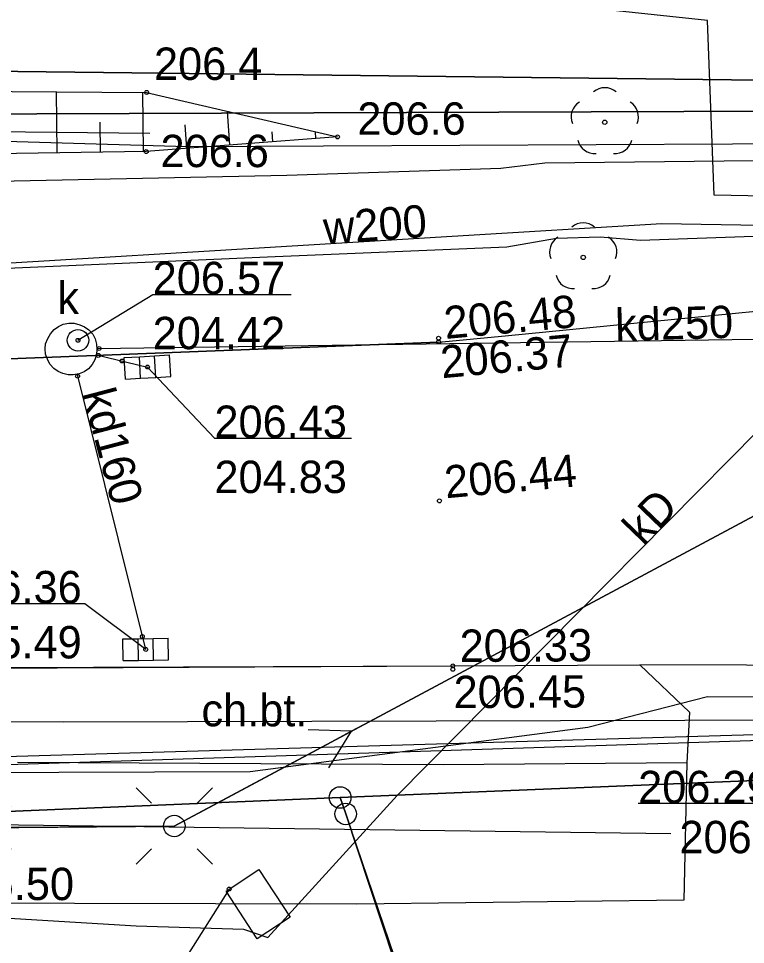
# Model space of a CAD drawing. Extents: x 6512400 to 6513200, y 6022500 to 6022750.
# Drawn here: x 6512747.42 to 6512764.26, y 6022670.32 to 6022691.76 of the extents above; entities that cross this region are included whole.
import ezdxf

# ---------------------------------------------------------------- set-up
doc = ezdxf.new("R2010")
doc.units = 0
for name, color, linetype in [('202-punkt graniczny', 7, 'Continuous'), ('216-obręb ewidencyjny', 7, 'Continuous'), ('218-kontur użytku gruntowego', 7, 'Continuous'), ('219-działka ewidencyjna', 7, 'Continuous'), ('820-Skarpa nieumocniona', 7, 'Continuous'), ('823-Szczyt skarpy nieumocninej', 7, 'Continuous'), ('824-Podnóże skarpy nieumocninej', 7, 'Continuous'), ('903-Żywopłot', 7, 'Continuous'), ('chodnik', 7, 'Continuous'), ('chodnik (powierzchnia)', 7, 'Continuous'), ('chodnik (powierzchnia)-Atr17', 7, 'Continuous'), ('drzewo liściaste (punkt)', 7, 'Continuous'), ('inny obiekt zagospodarowania terenu', 7, 'Continuous'), ('jezdnia (powierzchnia)', 7, 'Continuous'), ('komora podziemna - przewód kanalizacyjny (powierzchnia)', 7, 'Continuous'), ('kratka ściekowa (punkt)', 7, 'Continuous'), ('krawężnik (linia)', 7, 'Continuous'), ('latarnia na słupie lub maszcie (punkt)', 7, 'Continuous'), ('pikieta sztuczna-Atr2', 7, 'Continuous'), ('przewód elektroenergetyczny (linia)', 7, 'Continuous'), ('przewód elektroenergetyczny niskiego napięcia (linia)', 7, 'Continuous'), ('przewód elektroenergetyczny niskiego napięcia (linia) - symbol', 7, 'Continuous'), ('przewód gazowy (linia)', 7, 'Continuous'), ('przewód kanalizacyjny (linia)', 7, 'Continuous'), ('przewód kanalizacyjny (linia)-Atr1', 7, 'Continuous'), ('przewód telekomunikacyjny (linia)', 7, 'Continuous'), ('przewód wodociągowy (linia)', 7, 'Continuous'), ('przewód wodociągowy (linia)-Atr1', 7, 'Continuous'), ('punkt o określonej wysokości (sieć kanalizacyjna)', 7, 'Continuous'), ('punkt o określonej wysokości (sieć kanalizacyjna)-Atr2', 7, 'Continuous'), ('punkt o określonej wysokości (sieć kanalizacyjna)-Atr3', 7, 'Continuous'), ('punkt o określonej wysokości (sieć wodociągowa)-Atr2', 7, 'Continuous'), ('punkt wysokościowy naturalny', 7, 'Continuous'), ('punkt wysokościowy naturalny-Atr2', 7, 'Continuous'), ('punkt wysokościowy sztuczny', 7, 'Continuous'), ('punkt wysokościowy sztuczny-Atr2', 7, 'Continuous'), ('słup (punkt)', 7, 'Continuous'), ('właz okrągły - siec kanalizacyjna (punkt)', 7, 'Continuous'), ('właz okrągły - siec kanalizacyjna (punkt)-Atr17', 7, 'Continuous')]:
    doc.layers.add(name, color=color, linetype=linetype)

# ---------------------------------------------------------------- blocks, each defined once
blk = doc.blocks.new('202')
blk.add_circle((0, 0), 0.25)
blk = doc.blocks.new('PW01')
blk.add_circle((0, 0), 0.045)
blk = doc.blocks.new('OP021')
blk.add_circle((0, 0), 0.05)
for centre, start, end in [((0, 0.4), 49.272, 130.728), ((-0.38, 0.124), 121.308, 202.548), ((0.38, 0.124), 337.452, 58.692), ((-0.235, -0.324), 193.221, 274.871), ((0.235, -0.324), 265.129, 346.779)]:
    blk.add_arc(centre, 0.4, start, end)
blk = doc.blocks.new('US22')
blk.add_circle((0, 0), 0.25)
blk = doc.blocks.new('US05')
for p, q in [((-0.525, -0.25), (-0.525, 0.25)), ((-0.525, 0.25), (-0.175, 0.25)), ((-0.175, -0.25), (-0.175, 0.25)), ((-0.175, 0.25), (0.175, 0.25)), ((0.175, -0.25), (0.175, 0.25)), ((0.175, 0.25), (0.525, 0.25)), ((0.525, -0.25), (0.525, 0.25)), ((-0.525, -0.25), (-0.175, -0.25)), ((-0.175, -0.25), (0.175, -0.25)), ((0.175, -0.25), (0.525, -0.25))]:
    blk.add_line(p, q)
blk = doc.blocks.new('PW02')
blk.add_circle((0, 0), 0.045)
blk = doc.blocks.new('PE04')
for p, q in [((4.65, 0), (3.784, 0.5)), ((0.65, 0), (0, 0)), ((0.65, 0), (1.65, 0)), ((1.65, 0), (2.65, 0)), ((2.65, 0), (3.65, 0)), ((3.65, 0), (4.65, 0)), ((4.65, 0), (3.784, -0.5)), ((4.65, 0), (5, 0))]:
    blk.add_line(p, q)
blk = doc.blocks.new('SM011')
for p, q in [((-0.53, 0.531), (-0.883, 0.884)), ((0.531, 0.531), (0.884, 0.884)), ((-0.53, -0.53), (-0.883, -0.883)), ((0.531, -0.53), (0.884, -0.883))]:
    blk.add_line(p, q)
blk = doc.blocks.new('SM04')
blk.add_circle((0, 0), 0.25)

msp = doc.modelspace()

# ---------------------------------------------------------------- linework, layer by layer
at = {"layer": '216-obręb ewidencyjny'}
for points in [[(6512688.62, 6022674.91), (6512702.58, 6022674.18), (6512725.78, 6022672.95), (6512730.35, 6022672.71), (6512735.76, 6022672.94), (6512745.51, 6022673.33), (6512754.87, 6022673.72), (6512768.24, 6022674.27), (6512785.56, 6022674.74), (6512790.49, 6022674.74), (6512796.96, 6022674.74), (6512801.96, 6022670.34), (6512828.67, 6022670.98), (6512833.61, 6022675.02), (6512836.69, 6022675.17), (6512851.94, 6022675.93)], [(6512785.56, 6022674.74), (6512768.24, 6022674.27), (6512754.87, 6022673.72), (6512745.51, 6022673.33), (6512735.76, 6022672.94), (6512730.35, 6022672.71), (6512725.78, 6022672.95), (6512702.575, 6022674.177)]]:
    msp.add_lwpolyline(points, dxfattribs=at)
at = {"layer": '218-kontur użytku gruntowego'}
for points in [[(6512706.4, 6022691.01), (6512787.08, 6022690.07)], [(6512787.08, 6022690.07), (6512706.4, 6022691.01)], [(6512768.24, 6022674.27), (6512754.87, 6022673.72)], [(6512754.87, 6022673.72), (6512768.24, 6022674.27)], [(6512754.87, 6022673.72), (6512745.51, 6022673.33)], [(6512745.51, 6022673.33), (6512754.87, 6022673.72)], [(6512755, 6022673.34), (6512754.87, 6022673.72)], [(6512754.87, 6022673.72), (6512755, 6022673.34)], [(6512757.8, 6022664.88), (6512755, 6022673.34)], [(6512755, 6022673.34), (6512757.8, 6022664.88)]]:
    msp.add_lwpolyline(points, dxfattribs=at)
at = {"layer": '219-działka ewidencyjna'}
for points in [[(6512706.4, 6022691.01), (6512787.08, 6022690.07)], [(6512768.24, 6022674.27), (6512754.87, 6022673.72)], [(6512754.87, 6022673.72), (6512745.51, 6022673.33)], [(6512754.87, 6022673.72), (6512755, 6022673.34)], [(6512762.17, 6022652.29), (6512755, 6022673.34)]]:
    msp.add_lwpolyline(points, dxfattribs=at)
at = {"layer": '820-Skarpa nieumocniona'}
for p, q in [((6512748.32, 6022688.65), (6512748.3, 6022690.07)), ((6512750.32, 6022688.68), (6512750.3, 6022690.05)), ((6512752.32, 6022688.83), (6512752.26, 6022689.61)), ((6512749.32, 6022688.66), (6512749.31, 6022689.36)), ((6512751.32, 6022688.75), (6512751.28, 6022689.3)), ((6512753.31, 6022688.91), (6512753.3, 6022689.14)), ((6512754.31, 6022688.98), (6512754.3, 6022689.14))]:
    msp.add_line(p, q, dxfattribs=at)
at = {"layer": '823-Szczyt skarpy nieumocninej'}
msp.add_lwpolyline([(6512754.81, 6022689.02), (6512750.38, 6022688.68), (6512731.85, 6022688.4), (6512721.27, 6022688.58), (6512714.51, 6022690.92)], dxfattribs=at)
at = {"layer": '824-Podnóże skarpy nieumocninej'}
msp.add_lwpolyline([(6512714.51, 6022690.92), (6512719.59, 6022690.77), (6512731.72, 6022690.19), (6512750.39, 6022690.05), (6512754.81, 6022689.02)], dxfattribs=at)
at = {"layer": '903-Żywopłot'}
msp.add_lwpolyline([(6512750.46, 6022689.1), (6512732.44, 6022689.29)], dxfattribs=at)
at = {"layer": 'chodnik'}
msp.add_lwpolyline([(6512768.44, 6022668.05), (6512768.21, 6022674.06), (6512768.22, 6022675.69), (6512769.23, 6022676.77), (6512761.81, 6022676.79), (6512762.96, 6022675.7), (6512762.9, 6022674.52), (6512762.83, 6022671.34), (6512755.26, 6022671.25), (6512745.44, 6022671.27), (6512745.37, 6022673.33), (6512745.36, 6022673.75), (6512745.04, 6022673.58), (6512744.23, 6022673.02), (6512743.49, 6022672.33), (6512742.93, 6022671.51), (6512742.59, 6022670.47), (6512743.54, 6022669.87)], dxfattribs=at)
at = {"layer": 'chodnik (powierzchnia)'}
for points in [[(6512786.39, 6022689.96), (6512786.43, 6022689.56), (6512785.75, 6022688.59), (6512780.55, 6022688.53), (6512773.92, 6022688.46), (6512772.96, 6022688.47), (6512771.38, 6022688.54), (6512759.61, 6022688.41), (6512758.59, 6022688.29), (6512753.64, 6022688.13), (6512742.85, 6022687.9), (6512740.21, 6022687.75), (6512727.76, 6022687.39)], [(6512770.26, 6022685.56), (6512768.81, 6022686.87), (6512761.83, 6022686.62), (6512760.89, 6022686.7), (6512759.88, 6022686.67), (6512758.73, 6022686.47), (6512753.37, 6022686.24), (6512740.24, 6022685.67), (6512727.63, 6022685.27)], [(6512747.08, 6022676.73), (6512757.48, 6022676.77), (6512761.81, 6022676.79), (6512762.96, 6022675.7), (6512762.9, 6022674.52), (6512757.26, 6022674.48), (6512747.4, 6022674.53)]]:
    msp.add_lwpolyline(points, dxfattribs=at)
at = {"layer": 'inny obiekt zagospodarowania terenu'}
msp.add_lwpolyline([(6512746.25, 6022673.1), (6512762.53, 6022672.89)], dxfattribs=at)
at = {"layer": 'jezdnia (powierzchnia)'}
for points in [[(6512707.74, 6022685), (6512715.41, 6022684.53), (6512729.72, 6022683.88), (6512743.02, 6022683.72), (6512757.15, 6022684.27)], [(6512707.08, 6022677.87), (6512714.85, 6022677.5), (6512727.62, 6022676.91), (6512733.49, 6022676.74), (6512737.49, 6022676.65), (6512740.34, 6022676.65), (6512746.78, 6022676.72), (6512757.48, 6022676.77)]]:
    msp.add_lwpolyline(points, dxfattribs=at)
at = {"layer": 'komora podziemna - przewód kanalizacyjny (powierzchnia)'}
for points in [[(6512749.24, 6022684.1), (6512749.23, 6022683.98), (6512749.19, 6022683.86), (6512749.13, 6022683.75), (6512749.04, 6022683.65), (6512748.94, 6022683.58), (6512748.83, 6022683.53), (6512748.69, 6022683.51), (6512748.57, 6022683.51), (6512748.45, 6022683.54), (6512748.34, 6022683.59), (6512748.24, 6022683.66), (6512748.15, 6022683.76), (6512748.09, 6022683.87), (6512748.05, 6022683.99), (6512748.04, 6022684.11), (6512748.05, 6022684.23), (6512748.1, 6022684.35), (6512748.16, 6022684.46), (6512748.25, 6022684.56), (6512748.35, 6022684.63), (6512748.46, 6022684.68), (6512748.59, 6022684.71), (6512748.71, 6022684.71), (6512748.84, 6022684.67), (6512748.95, 6022684.62), (6512749.05, 6022684.55), (6512749.14, 6022684.45), (6512749.2, 6022684.34), (6512749.23, 6022684.22)], [(6512752.95, 6022670.45), (6512752.23, 6022671.55), (6512752.99, 6022672.05), (6512753.71, 6022670.95)]]:
    msp.add_lwpolyline(points, close=True, dxfattribs=at)
at = {"layer": 'krawężnik (linia)'}
for points in [[(6512757.15, 6022684.27), (6512758.69, 6022684.41), (6512769.83, 6022685.51), (6512772.56, 6022685.82), (6512777.4, 6022686.23), (6512782.53, 6022686.49), (6512786.32, 6022686.51), (6512790.79, 6022686.51)], [(6512757.15, 6022684.27), (6512743.02, 6022683.72), (6512729.72, 6022683.88), (6512715.41, 6022684.53), (6512707.74, 6022685)], [(6512707.08, 6022677.87), (6512714.85, 6022677.5), (6512727.62, 6022676.91), (6512733.49, 6022676.74), (6512737.49, 6022676.65), (6512740.34, 6022676.65), (6512746.78, 6022676.72), (6512757.48, 6022676.77)], [(6512757.48, 6022676.77), (6512761.81, 6022676.79)]]:
    msp.add_lwpolyline(points, dxfattribs=at)
at = {"layer": 'przewód elektroenergetyczny (linia)'}
for points in [[(6512731.37, 6022676.71), (6512731.37, 6022675.58), (6512748.46, 6022675.47), (6512780.13, 6022675.56), (6512787.87, 6022675.5)], [(6512702.569, 6022673.878), (6512710.28, 6022673.25), (6512716.66, 6022675.97), (6512746.13, 6022674.3), (6512752.79, 6022674.32), (6512760.61, 6022675.35), (6512763.38, 6022676.06), (6512798.79, 6022676.04)], [(6512702.603, 6022675.567), (6512731.84, 6022674.22), (6512765.79, 6022675.22), (6512787.87, 6022675.5)]]:
    msp.add_lwpolyline(points, dxfattribs=at)
at = {"layer": 'przewód elektroenergetyczny niskiego napięcia (linia)'}
for points in [[(6512782.09, 6022689.68), (6512702.887, 6022689.392)], [(6512702.887, 6022689.392), (6512782.09, 6022689.68)], [(6512751.03, 6022673.06), (6512782.09, 6022689.68)], [(6512782.09, 6022689.68), (6512751.03, 6022673.06)], [(6512719.56, 6022672.79), (6512751.03, 6022673.06)]]:
    msp.add_lwpolyline(points, dxfattribs=at)
at = {"layer": 'przewód gazowy (linia)'}
msp.add_lwpolyline([(6512790.27, 6022690.86), (6512788.32, 6022687.6), (6512767.44, 6022687.59), (6512763.53, 6022687.67), (6512763.38, 6022691.72), (6512760.4, 6022692.03), (6512740.79, 6022692.33), (6512723.64, 6022692.06), (6512711.62, 6022691.95), (6512703.17, 6022690.39), (6512702.97, 6022685.4), (6512702.78, 6022684.183)], dxfattribs=at)
at = {"layer": 'przewód kanalizacyjny (linia)'}
for points in [[(6512749.24, 6022684.12), (6512782.48, 6022684.59)], [(6512756.19, 6022673.77), (6512766.65, 6022684.34)], [(6512749.23, 6022683.97), (6512750.41, 6022683.69)], [(6512750.37, 6022677.15), (6512748.79, 6022683.52)], [(6512753.2, 6022670.48), (6512756.19, 6022673.77)], [(6512716.83, 6022672.25), (6512720.83, 6022672.11), (6512730.47, 6022671.7), (6512737.04, 6022671.58), (6512738.87, 6022671.48), (6512744.52, 6022671.09), (6512750.15, 6022670.75), (6512752.63, 6022670.67), (6512753.2, 6022670.48)]]:
    msp.add_lwpolyline(points, dxfattribs=at)
at = {"layer": 'przewód telekomunikacyjny (linia)'}
msp.add_lwpolyline([(6512786.53, 6022688.5), (6512773.43, 6022688.9), (6512751.33, 6022688.79), (6512741.32, 6022689.08), (6512718.97, 6022688.75), (6512713.12, 6022690.07), (6512711.25, 6022690.1), (6512706.82, 6022689.08), (6512704.98, 6022689.07)], dxfattribs=at)
at = {"layer": 'przewód wodociągowy (linia)'}
for points in [[(6512777.27, 6022686.75), (6512776.94, 6022686.76), (6512762.32, 6022687.01), (6512742.89, 6022685.83), (6512741.87, 6022684.29)], [(6512702.579, 6022674.359), (6512731.63, 6022673.98), (6512765.81, 6022675.09), (6512780.05, 6022675.09), (6512787.64, 6022675.26)]]:
    msp.add_lwpolyline(points, dxfattribs=at)
at = {"layer": 'punkt o określonej wysokości (sieć kanalizacyjna)-Atr2'}
for points in [[(6512748.8, 6022684.31), (6512750.53, 6022685.37), (6512753.734, 6022685.37)], [(6512750.41, 6022683.69), (6512751.96, 6022682.04), (6512755.133, 6022682.04)], [(6512750.37, 6022677.15), (6512748.96, 6022678.21), (6512745.819, 6022678.21)], [(6512752.3, 6022671.6), (6512750.58, 6022668.87), (6512747.445, 6022668.87)]]:
    msp.add_lwpolyline(points, dxfattribs=at)
at = {"layer": 'punkt o określonej wysokości (sieć wodociągowa)-Atr2'}
msp.add_lwpolyline([(6512765.81, 6022675.09), (6512764.85, 6022673.58), (6512761.773, 6022673.58)], dxfattribs=at)

# ---------------------------------------------------------------- block references
at = {"layer": '202-punkt graniczny'}
for p in [(6512754.87, 6022673.72), (6512755, 6022673.34)]:
    msp.add_blockref('202', p, dxfattribs=at)
at = {"layer": 'drzewo liściaste (punkt)'}
for p in [(6512761, 6022689.36), (6512760.5, 6022686.23)]:
    msp.add_blockref('OP021', p, dxfattribs=at)
at = {"layer": 'kratka ściekowa (punkt)'}
for p, rotation in [((6512750.41, 6022683.69), 3.27), ((6512750.37, 6022677.15), 0.807)]:
    msp.add_blockref('US05', p, dxfattribs=dict(at, rotation=rotation))
at = {"layer": 'latarnia na słupie lub maszcie (punkt)'}
msp.add_blockref('SM011', (6512751.03, 6022673.06), dxfattribs=at)
at = {"layer": 'przewód elektroenergetyczny niskiego napięcia (linia) - symbol'}
for rotation in [28.151, -179.50800000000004]:
    msp.add_blockref('PE04', (6512751.03, 6022673.06), dxfattribs=dict(at, rotation=rotation))
at = {"layer": 'punkt o określonej wysokości (sieć kanalizacyjna)'}
for p in [(6512748.8, 6022684.31), (6512752.3, 6022671.6)]:
    msp.add_blockref('PW01', p, dxfattribs=at)
for p, rotation in [((6512749.29, 6022684.12), 1.62), ((6512749.27, 6022683.96), -12.425999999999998), ((6512749.82, 6022683.83), -12.425999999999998), ((6512750.41, 6022683.69), 3.27), ((6512748.79, 6022683.48), -75.265), ((6512750.29, 6022677.45), -75.265), ((6512750.37, 6022677.15), 0.807)]:
    msp.add_blockref('PW01', p, dxfattribs=dict(at, rotation=rotation))
at = {"layer": 'punkt wysokościowy naturalny'}
for p in [(6512750.39, 6022690.05), (6512754.81, 6022689.02), (6512750.38, 6022688.68)]:
    msp.add_blockref('PW01', p, dxfattribs=at)
at = {"layer": 'punkt wysokościowy sztuczny'}
for p in [(6512757.15, 6022684.36), (6512757.15, 6022684.27), (6512757.17, 6022680.59), (6512757.48, 6022676.77), (6512757.48, 6022676.69)]:
    msp.add_blockref('PW02', p, dxfattribs=at)
at = {"layer": 'słup (punkt)'}
msp.add_blockref('SM04', (6512751.03, 6022673.06), dxfattribs=at)
at = {"layer": 'właz okrągły - siec kanalizacyjna (punkt)'}
msp.add_blockref('US22', (6512748.8, 6022684.31), dxfattribs=at)

# ---------------------------------------------------------------- texts
at = {"layer": 'chodnik (powierzchnia)-Atr17'}
msp.add_text('ch.bt.', height=0.75, dxfattribs=at).set_placement((6512751.66, 6022675.37))
at = {"layer": 'pikieta sztuczna-Atr2'}
msp.add_text('206.35', height=0.75, dxfattribs=at).set_placement((6512762.73, 6022672.43))
at = {"layer": 'przewód kanalizacyjny (linia)-Atr1'}
for s, rotation, p in [('kd250', 1.631, (6512761.25, 6022684.29)), ('kd160', 284.715, (6512748.9, 6022683.09)), ('kD', 46.112, (6512761.89, 6022679.53))]:
    msp.add_text(s, height=0.75, rotation=rotation, dxfattribs=at).set_placement(p)
at = {"layer": 'przewód wodociągowy (linia)-Atr1'}
msp.add_text('w200', height=0.75, rotation=4.273, dxfattribs=at).set_placement((6512754.51, 6022686.53))
at = {"layer": 'punkt o określonej wysokości (sieć kanalizacyjna)-Atr2'}
for s, p in [('206.57', (6512750.53, 6022685.378)), ('206.43', (6512751.96, 6022682.048)), ('206.36', (6512745.819, 6022678.218))]:
    msp.add_text(s, height=0.75, dxfattribs=at).set_placement(p)
at = {"layer": 'punkt o określonej wysokości (sieć kanalizacyjna)-Atr3'}
for s, p in [('204.42', (6512750.53, 6022684.103)), ('204.83', (6512751.96, 6022680.772)), ('205.49', (6512745.819, 6022676.942))]:
    msp.add_text(s, height=0.75, dxfattribs=at).set_placement(p)
at = {"layer": 'punkt o określonej wysokości (sieć wodociągowa)-Atr2'}
msp.add_text('206.29', height=0.75, dxfattribs=at).set_placement((6512761.773, 6022673.588))
at = {"layer": 'punkt wysokościowy naturalny-Atr2'}
for s, p in [('206.4', (6512750.56, 6022690.34)), ('206.6', (6512755.27, 6022689.07)), ('206.6', (6512750.71, 6022688.32))]:
    msp.add_text(s, height=0.75, dxfattribs=at).set_placement(p)
at = {"layer": 'punkt wysokościowy sztuczny-Atr2'}
for s, rotation, p in [('206.48', 5.194, (6512757.31, 6022684.34)), ('206.37', 5.194, (6512757.23, 6022683.43)), ('206.44', 5.194, (6512757.32, 6022680.65)), ('206.33', 0.264, (6512757.64, 6022676.86)), ('206.45', 0.264, (6512757.5, 6022675.79)), ('206.50', 359.883, (6512745.64, 6022671.35))]:
    msp.add_text(s, height=0.75, rotation=rotation, dxfattribs=at).set_placement(p)
at = {"layer": 'właz okrągły - siec kanalizacyjna (punkt)-Atr17'}
msp.add_text('k', height=0.75, dxfattribs=at).set_placement((6512748.32, 6022684.92))

doc.saveas('drawing.dxf')
